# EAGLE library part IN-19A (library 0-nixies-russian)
IN-19A: medium symbol frontview nixie tube
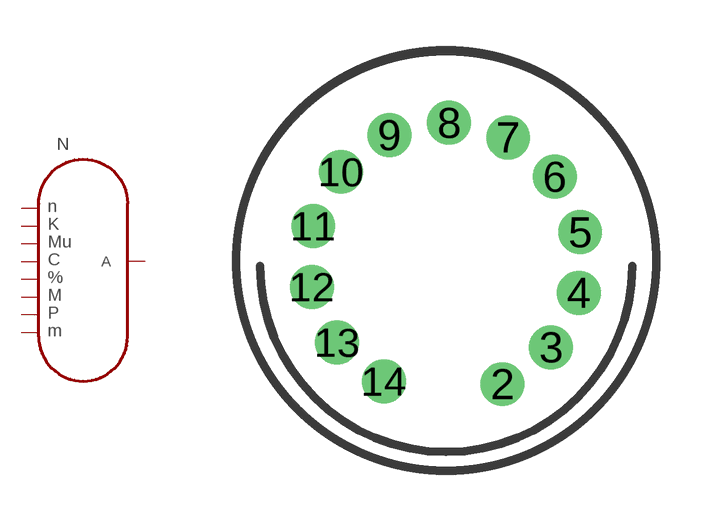
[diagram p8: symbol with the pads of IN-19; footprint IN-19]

Designator prefix N

## IN-19A  [IN-19]
2  P$5
4  P$6
5  P$7
6  P$8
8  A
10  P$2
11  P$1
12  P$3
14  P$4

## Footprint IN-19 (pad centres in mm)
drill 0.84 round: 2 1.733,-3.786; 3 3.222,-2.652; 4 4.072,-0.985; 5 4.114,0.886; 6 3.34,2.59; 7 1.903,3.79; 8 0.089,4.247; 9 -1.745,3.872; 10 -3.234,2.738; 11 -4.084,1.07; 12 -4.126,-0.801; 13 -3.352,-2.505; 14 -1.915,-3.704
